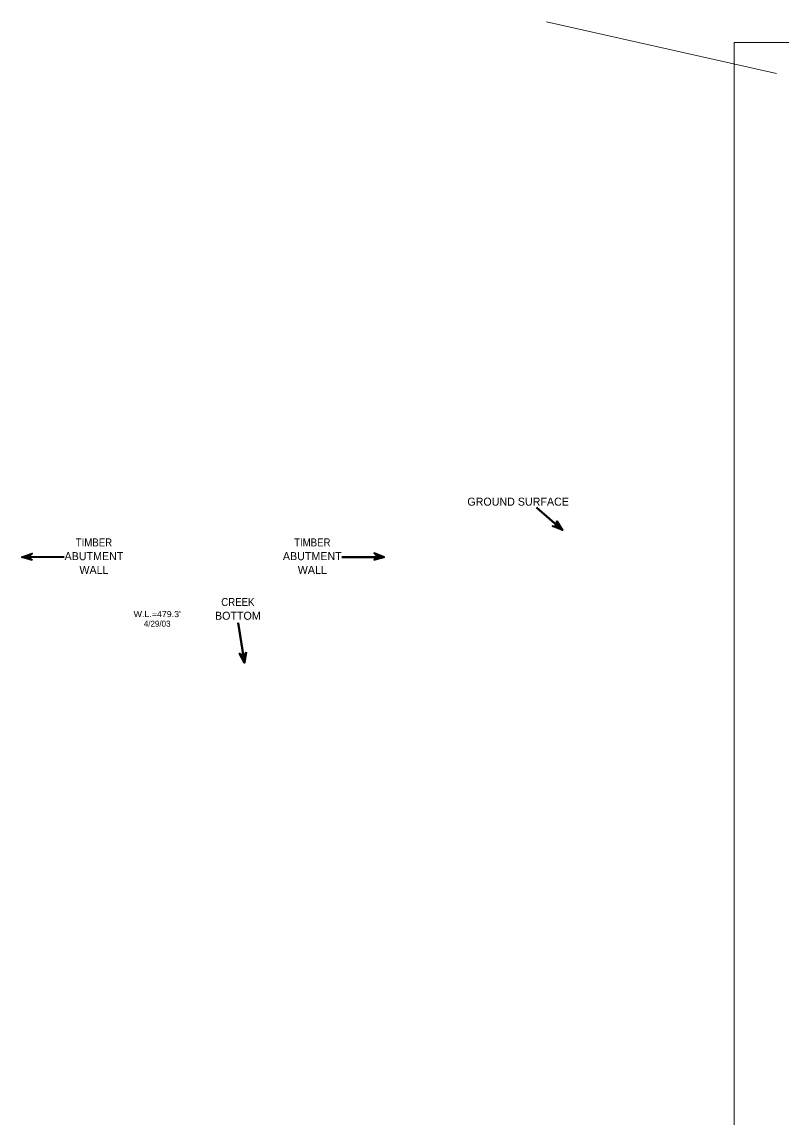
# Model space of a CAD drawing. Extents: x -582 to 653, y -817 to -3.
# Drawn here: x -280.4 to -207.1, y -263.1 to -157.5 of the extents above; entities that cross this region are included whole.
import ezdxf
from ezdxf.enums import TextEntityAlignment as Align

# ---------------------------------------------------------------- set-up
doc = ezdxf.new("R2010")
doc.units = 0
doc.header["$LTSCALE"] = 0.4
for name, color, linetype, lineweight in [('10', 7, 'Continuous', 35), ('27', 7, 'Continuous', 40), ('63', 7, 'Continuous', 35)]:
    doc.layers.add(name, color=color, linetype=linetype, lineweight=lineweight)

msp = doc.modelspace()

# ---------------------------------------------------------------- hatches: boundary and pattern name
at = {"layer": '10'}
for points in [[(-228.7321, -205.6155), (-228.1945, -206.5131), (-229.1629, -206.1177), (-228.6965, -206.0819)], [(-279.3627, -209.4179), (-280.3649, -209.1179), (-279.3833, -208.7567), (-279.7037, -209.0977)], [(-246.4135, -209.3919), (-245.4037, -209.1181), (-246.3755, -208.7315), (-246.0643, -209.0805)], [(-258.7257, -218.2857), (-258.8871, -219.3195), (-259.3781, -218.3959), (-258.9967, -218.6671)]]:
    msp.add_hatch(color=256, dxfattribs=at).paths.add_polyline_path(points)

# ---------------------------------------------------------------- linework, layer by layer
for points in [[(-228.7321, -205.6155), (-228.1945, -206.5131), (-229.1629, -206.1177), (-228.6965, -206.0819)], [(-279.3627, -209.4179), (-280.3649, -209.1179), (-279.3833, -208.7567), (-279.7037, -209.0977)], [(-246.4135, -209.3919), (-245.4037, -209.1181), (-246.3755, -208.7315), (-246.0643, -209.0805)], [(-258.7257, -218.2857), (-258.8871, -219.3195), (-259.3781, -218.3959), (-258.9967, -218.6671)]]:
    msp.add_lwpolyline(points, close=True, dxfattribs=at)
at = {"layer": '27', "lineweight": 13}
msp.add_line((-207.5589, -162.4726), (-229.7488, -157.501), dxfattribs=at)
at = {"layer": '27'}
for p, q in [((-228.1942, -206.5128), (-230.7146, -204.3305)), ((-280.3651, -209.1179), (-276.2794, -209.0848)), ((-245.4036, -209.118), (-249.496, -209.1088)), ((-258.8869, -219.3192), (-259.4842, -215.45))]:
    msp.add_line(p, q, dxfattribs=at)
at = {"layer": '63', "lineweight": 13}
for q in [(-211.6418, -329.4952), (-101.6418, -159.4952)]:
    msp.add_line((-211.6418, -159.4952), q, dxfattribs=at)

# ---------------------------------------------------------------- texts
at = {"layer": '27'}
for s, height, p in [('GROUND SURFACE', 0.7717, (-232.4777, -204.1531)), ('ABUTMENT', 0.7717, (-273.4107, -209.4083)), ('ABUTMENT', 0.7717, (-252.3401, -209.4083)), ('WALL', 0.7717, (-273.4105, -210.7313)), ('WALL', 0.7717, (-252.3401, -210.7313)), ('BOTTOM', 0.7717, (-259.5233, -215.1555)), ('4/29/03', 0.5788, (-267.3091, -215.8273))]:
    msp.add_text(s, height=height, dxfattribs=at).set_placement(p, align=Align.CENTER)
for s, height, width, p in [('TIMBER', 0.7717, 0.9, (-273.4107, -208.0853)), ('TIMBER', 0.7717, 0.9, (-252.3401, -208.0853)), ('CREEK', 0.7717, 0.9, (-259.5236, -213.8325)), ("W.L.=479.3'", 0.5788, 1.1, (-267.3091, -214.9025))]:
    msp.add_text(s, height=height, dxfattribs=dict(at, width=width)).set_placement(p, align=Align.CENTER)

doc.saveas('drawing.dxf')
